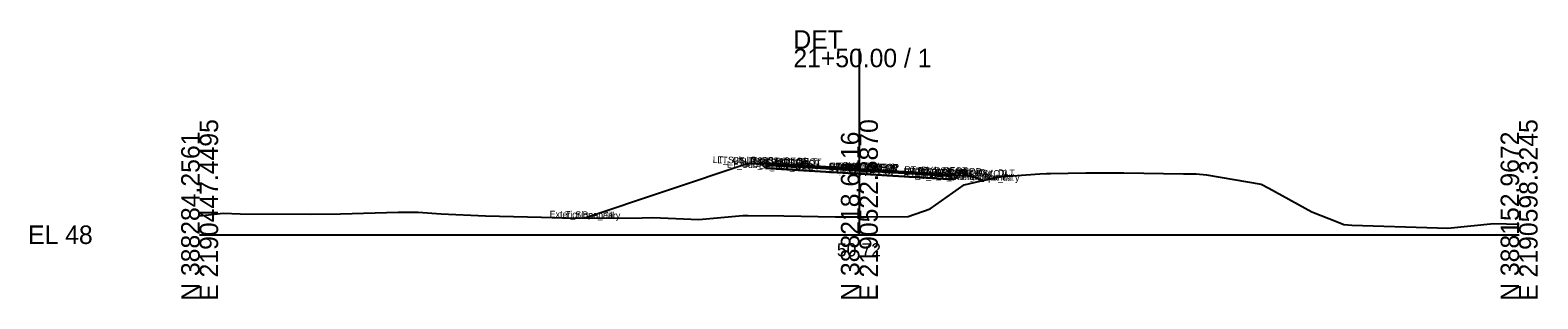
# Model space of a CAD drawing. Extents: x -26 to 1203, y -10 to 9543.
# Drawn here: x 974.3 to 1202.8, y 1490.3 to 1530.9 of the extents above; entities that cross this region are included whole.
import ezdxf

# ---------------------------------------------------------------- set-up
doc = ezdxf.new("R2010")
doc.units = 0
for name, color, linetype in [('Default', 7, 'Continuous'), ('Exist Cross Section Cell', 7, 'Continuous'), ('Exist XS Center Line Elevation Label', 7, 'Continuous'), ('Exist XS Ground Line', 7, 'Continuous'), ('Prop CMT Pvmt Course 1', 7, 'Continuous'), ('Prop CMT Pvmt Course 2', 7, 'Continuous'), ('Prop CMT Pvmt Course 3', 7, 'Continuous'), ('Prop CMT Pvmt Surface', 7, 'Continuous'), ('Prop CMT Pvmt Surface Shoulder', 7, 'Continuous'), ('Prop CMT Shld Paved Course 1', 7, 'Continuous'), ('Prop CMT Shld Paved Course 2', 7, 'Continuous'), ('Prop CMT Shld Paved Course 3', 7, 'Continuous'), ('Prop CMT Slope Grass', 7, 'Continuous'), ('Prop CMT Subgrade Earthwork', 7, 'Continuous'), ('Scratch_Level_0', 7, 'Continuous')]:
    doc.layers.add(name, color=color, linetype=linetype)

msp = doc.modelspace()

# ---------------------------------------------------------------- linework, layer by layer
at = {"layer": 'Exist Cross Section Cell'}
for p, q in [((1100, 1500), (1100, 1528.14)), ((1000, 1500), (1100, 1500)), ((1100, 1500), (1200, 1500))]:
    msp.add_line(p, q, dxfattribs=at)
at = {"layer": 'Exist XS Ground Line'}
for p, q in [((1118.28, 1508.09), (1122.09, 1508.89)), ((1122.09, 1508.89), (1123.23, 1508.92)), ((1123.23, 1508.92), (1127.36, 1509.2)), ((1127.36, 1509.2), (1128.36, 1509.26)), ((1128.36, 1509.26), (1128.98, 1509.28)), ((1128.98, 1509.28), (1134.34, 1509.34)), ((1134.34, 1509.34), (1140.09, 1509.38)), ((1140.09, 1509.38), (1149.13, 1509.22)), ((1149.13, 1509.22), (1151.05, 1509.19)), ((1151.05, 1509.19), (1152.6, 1509.05)), ((1152.6, 1509.05), (1160.91, 1507.65)), ((1110.72, 1503.94), (1115.89, 1507.53)), ((1115.89, 1507.53), (1118.28, 1508.09)), ((1160.91, 1507.65), (1162.04, 1507.04)), ((1162.04, 1507.04), (1168.57, 1503.48)), ((1107.39, 1502.76), (1110.72, 1503.94)), ((1000, 1502.86), (1003.58, 1503.24)), ((1003.58, 1503.24), (1006.14, 1503.18)), ((1006.14, 1503.18), (1016.84, 1503.13)), ((1016.84, 1503.13), (1021.37, 1503.17)), ((1021.37, 1503.17), (1030.09, 1503.41)), ((1030.09, 1503.41), (1033.13, 1503.43)), ((1033.13, 1503.43), (1036.61, 1503.18)), ((1036.61, 1503.18), (1043.35, 1502.84)), ((1043.35, 1502.84), (1051.84, 1502.68)), ((1051.84, 1502.68), (1056.61, 1502.52)), ((1056.61, 1502.52), (1067.08, 1502.58)), ((1067.08, 1502.58), (1068.57, 1502.6)), ((1068.57, 1502.6), (1069.87, 1502.54)), ((1069.87, 1502.54), (1075.66, 1502.28)), ((1075.66, 1502.28), (1082.31, 1502.89)), ((1082.31, 1502.89), (1083.12, 1502.92)), ((1083.12, 1502.92), (1088.55, 1502.84)), ((1088.55, 1502.84), (1096.38, 1502.71)), ((1096.38, 1502.71), (1097.61, 1502.71)), ((1097.61, 1502.71), (1100, 1502.72)), ((1100, 1502.72), (1101.26, 1502.73)), ((1101.26, 1502.73), (1107.39, 1502.76)), ((1168.57, 1503.48), (1172.58, 1501.88)), ((1172.58, 1501.88), (1173.41, 1501.53)), ((1173.41, 1501.53), (1174.62, 1501.43)), ((1189.18, 1501), (1196.17, 1501.7)), ((1196.17, 1501.7), (1200, 1501.6)), ((1174.62, 1501.43), (1187.61, 1501.04)), ((1187.61, 1501.04), (1189.18, 1501))]:
    msp.add_line(p, q, dxfattribs=at)
at = {"layer": 'Prop CMT Pvmt Course 1'}
for points in [[(1100, 1509.95), (1089, 1510.61)], [(1089, 1510.61), (1089, 1510.36)], [(1089, 1510.36), (1100, 1509.7)], [(1100, 1509.7), (1100, 1509.95)], [(1100, 1509.95), (1111, 1509.29)], [(1100, 1509.7), (1100, 1509.95)], [(1111, 1509.04), (1100, 1509.7)], [(1111, 1509.29), (1111, 1509.04)]]:
    msp.add_lwpolyline(points, dxfattribs=at)
msp.add_lwpolyline([(1100, 1509.7), (1100, 1509.82), (1100, 1509.82), (1100, 1509.7)], close=True, dxfattribs=at)
msp.add_lwpolyline([(1100, 1509.7), (1100, 1509.82), (1100, 1509.82), (1100, 1509.7)], close=True, dxfattribs=at)
at = {"layer": 'Prop CMT Pvmt Course 2'}
for points in [[(1089, 1510.36), (1100, 1509.7)], [(1100, 1509.7), (1089, 1510.36)], [(1089, 1510.36), (1089, 1510.36)], [(1100, 1509.7), (1100, 1509.7)], [(1111, 1509.04), (1100, 1509.7)], [(1100, 1509.7), (1100, 1509.7)], [(1100, 1509.7), (1111, 1509.04)], [(1111, 1509.04), (1111, 1509.04)]]:
    msp.add_lwpolyline(points, dxfattribs=at)
at = {"layer": 'Prop CMT Pvmt Course 3'}
for points in [[(1100, 1509.7), (1089, 1510.36)], [(1089, 1510.36), (1089, 1509.86)], [(1089, 1509.86), (1100, 1509.2)], [(1100, 1509.2), (1100, 1509.7)], [(1100, 1509.7), (1111, 1509.04)], [(1100, 1509.2), (1100, 1509.7)], [(1111, 1508.54), (1100, 1509.2)], [(1111, 1509.04), (1111, 1508.54)]]:
    msp.add_lwpolyline(points, dxfattribs=at)
at = {"layer": 'Prop CMT Pvmt Surface'}
for points in [[(1100, 1509.95), (1089, 1510.61)], [(1100, 1509.95), (1111, 1509.29)]]:
    msp.add_lwpolyline(points, dxfattribs=at)
at = {"layer": 'Prop CMT Pvmt Surface Shoulder'}
for points in [[(1089, 1510.61), (1087, 1510.73)], [(1111, 1509.29), (1113, 1509.17)]]:
    msp.add_lwpolyline(points, dxfattribs=at)
at = {"layer": 'Prop CMT Shld Paved Course 1'}
for points in [[(1089, 1510.61), (1087, 1510.73), (1086.76, 1510.49)], [(1089, 1510.36), (1089, 1510.61)], [(1086.76, 1510.49), (1089, 1510.36)], [(1111, 1509.29), (1113, 1509.17), (1113.27, 1508.9)], [(1111, 1509.04), (1111, 1509.29)], [(1113.27, 1508.9), (1111, 1509.04)]]:
    msp.add_lwpolyline(points, dxfattribs=at)
at = {"layer": 'Prop CMT Shld Paved Course 2'}
for points in [[(1089, 1510.36), (1086.76, 1510.49)], [(1086.76, 1510.49), (1086.76, 1510.49)], [(1086.76, 1510.49), (1089, 1510.36)], [(1089, 1510.36), (1089, 1510.36)], [(1111, 1509.04), (1113.27, 1508.9)], [(1113.27, 1508.9), (1111, 1509.04)], [(1111, 1509.04), (1111, 1509.04)], [(1113.27, 1508.9), (1113.27, 1508.9)]]:
    msp.add_lwpolyline(points, dxfattribs=at)
at = {"layer": 'Prop CMT Shld Paved Course 3'}
for points in [[(1089, 1510.36), (1086.76, 1510.49), (1086.26, 1510.52), (1085.79, 1510.05)], [(1085.79, 1510.05), (1089, 1509.86)], [(1089, 1509.86), (1089, 1510.36)], [(1111, 1509.04), (1113.27, 1508.9), (1113.77, 1508.87), (1114.3, 1508.34)], [(1111, 1508.54), (1111, 1509.04)], [(1114.3, 1508.34), (1111, 1508.54)]]:
    msp.add_lwpolyline(points, dxfattribs=at)
at = {"layer": 'Prop CMT Slope Grass'}
for points in [[(1087, 1510.73), (1083, 1510.73), (1058.39, 1502.53)], [(1113, 1509.17), (1117, 1508.85), (1118.89, 1508.22)]]:
    msp.add_lwpolyline(points, dxfattribs=at)
at = {"layer": 'Prop CMT Subgrade Earthwork'}
for points in [[(1085.79, 1510.05), (1085.11, 1510.73)], [(1089, 1509.86), (1085.79, 1510.05)], [(1100, 1509.2), (1089, 1509.86)], [(1100, 1509.2), (1111, 1508.54)], [(1111, 1508.54), (1114.3, 1508.34)], [(1114.3, 1508.34), (1114.97, 1509.01)]]:
    msp.add_lwpolyline(points, dxfattribs=at)

# ---------------------------------------------------------------- texts
at = {"layer": 'Default'}
msp.add_text('-', height=0.0001, dxfattribs=at).set_placement((1000, 1500))
at = {"layer": 'Exist Cross Section Cell'}
for s, p in [('DET', (1090, 1528.14)), ('21+50.00 / 1', (1090, 1525.34)), ('EL 48', (974, 1498.6))]:
    msp.add_text(s, height=2.8, dxfattribs=at).set_placement(p)
for s, p in [('N 388284.2561', (1000, 1490)), ('E 2190447.4495', (1002.8, 1490)), ('N 388218.6116', (1100, 1490)), ('E 2190522.8870', (1102.8, 1490)), ('N 388152.9672', (1200, 1490)), ('E 2190598.3245', (1202.8, 1490))]:
    msp.add_text(s, height=2.8, rotation=90, dxfattribs=at).set_placement(p)
at = {"layer": 'Exist XS Center Line Elevation Label'}
msp.add_text('50.72', height=2, dxfattribs=at).set_placement((1096.58, 1496.72))
at = {"layer": 'Scratch_Level_0'}
for s, p in [('LT_Sub_Trench_Out_DLT', (1077.77, 1510.87)), ('LT_GS_OS_CTL', (1078.46, 1510.82)), ('LT_Sub_Trench_Out', (1079.9, 1510.17)), ('LT_PS3_Shelf_Out', (1080.92, 1510.63)), ('LT_PS3_OEOP', (1082.55, 1510.58)), ('LT_PS2_OEOP', (1082.55, 1510.58)), ('LT_PS1_OEOP', (1082.91, 1510.81)), ('LT_PV2_OEOT', (1084.75, 1510.44)), ('LT_PV3_OEOT', (1084.75, 1510.44)), ('LT_Sub_OEOT', (1084.77, 1509.94)), ('LT_PV1_OEOT', (1084.87, 1510.69)), ('RT_PV2_OEEOP', (1095.33, 1509.79)), ('RT_PV3_OEEOP', (1095.33, 1509.79)), ('LT_PV2_OEEOP', (1095.39, 1509.79)), ('LT_PV3_OEEOP', (1095.39, 1509.79)), ('RT_PV1_OEEOP', (1095.45, 1509.91)), ('LT_PV1_OEEOP', (1095.51, 1509.91)), ('RT_PV2_IEEOP', (1095.71, 1509.78)), ('LT_PV2_IEEOP', (1095.77, 1509.78)), ('RT_PV1_IEEOP', (1095.83, 1509.91)), ('LT_PV1_IEEOP', (1095.89, 1509.9)), ('PV2_PGL', (1097.35, 1509.75)), ('PV1_PGL', (1097.47, 1510)), ('RT_Sub_OEEOP', (1095.36, 1509.29)), ('LT_Sub_OEEOP', (1095.42, 1509.29)), ('RT_PV3_OEOT', (1106.69, 1509.12)), ('RT_PV2_OEOT', (1106.69, 1509.12)), ('RT_Sub_OEOT', (1106.71, 1508.62)), ('RT_PV1_OEOT', (1106.81, 1509.37)), ('RT_Sub_Trench_Out_DLT', (1107.56, 1509.16)), ('RT_Sub_Trench_Out', (1108.35, 1508.46)), ('RT_PS3_Shelf_Out', (1108.37, 1508.98)), ('RT_PS1_OEOP', (1108.85, 1509.25)), ('RT_PS3_OEOP', (1108.99, 1508.99)), ('RT_PS2_OEOP', (1108.99, 1508.99)), ('RT_GS_OS_CTL', (1112.41, 1508.94)), ('Exterior Boundary', (1113.56, 1508.32)), ('RT_Slope_Fill', (1115.07, 1508.29)), ('Exterior Boundary', (1053.05, 1502.63)), ('LT_Slope_Fill', (1054.63, 1502.6))]:
    msp.add_text(s, height=1, rotation=358.8836, dxfattribs=at).set_placement(p)

doc.saveas('drawing.dxf')
